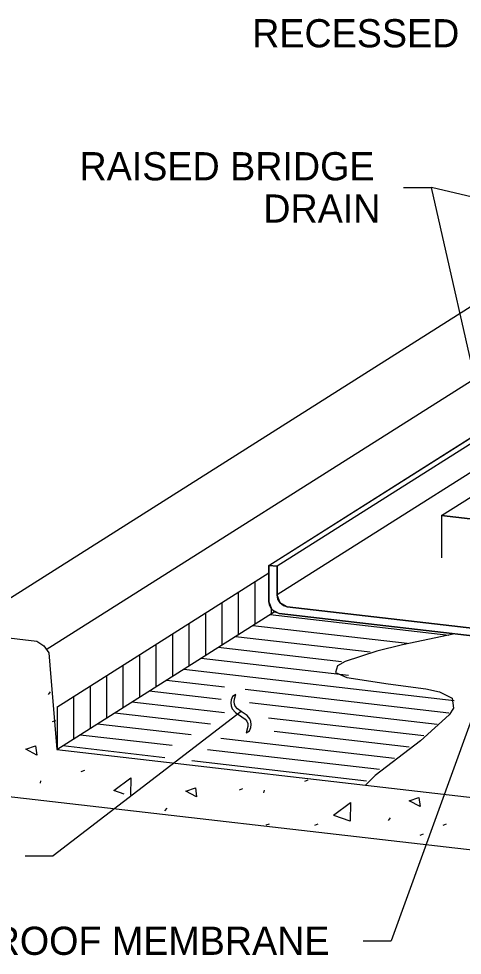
# Model space of a CAD drawing. Extents: x 99862 to 103151, y 100000 to 105076.
# Drawn here: x 102022 to 102274, y 103877 to 104409 of the extents above; entities that cross this region are included whole.
import ezdxf

# ---------------------------------------------------------------- set-up
doc = ezdxf.new("R2010")
doc.units = 0
for name, color, linetype in [('Level 1', 7, 'Continuous'), ('Level 15', 7, 'Continuous'), ('Level 20', 7, 'Continuous'), ('Level 3', 7, 'Continuous'), ('Level 4', 7, 'Continuous'), ('Level 7', 7, 'Continuous')]:
    doc.layers.add(name, color=color, linetype=linetype)

msp = doc.modelspace()

# ---------------------------------------------------------------- linework, layer by layer
at = {"layer": 'Level 1'}
for p, q in [((102262.02, 104126.8), (102262.02, 104102.75)), ((102163.91, 104098.53), (102168.59, 104097.99)), ((102163.91, 104080.79), (102163.91, 104098.53)), ((102163.91, 104077.87), (102163.91, 104080.79))]:
    msp.add_line(p, q, dxfattribs=at)
for points in [[(102481.21, 104118.78), (102369.43, 104048.12), (102169.65, 104071.2), (102167.45, 104071.91), (102165.59, 104073.42), (102164.35, 104075.52), (102163.91, 104077.87), (102163.91, 104098.53), (102350.74, 104216.63)], [(102163.91, 104077.87), (102163.91, 104080.79), (102163.91, 104098.53), (102350.24, 104216.31)], [(102350.24, 104212.81), (102168.59, 104097.99), (102168.59, 104081.69)], [(102350.24, 104196.51), (102168.59, 104081.69), (102169.03, 104079.34), (102170.27, 104077.24), (102172.13, 104075.73), (102174.33, 104075.02), (102369.43, 104052.48)], [(102262.02, 104126.8), (102303.73, 104153.17), (102352.43, 104147.54)], [(102262.02, 104126.8), (102310.72, 104121.17)], [(102310.72, 104097.12), (102310.72, 104121.17), (102262.02, 104126.8)], [(102163.91, 104098.53), (102163.91, 104077.87), (102163.91, 104077.87), (102165.59, 104073.42), (102169.65, 104071.2), (102169.65, 104071.2), (102369.43, 104048.12), (102369.43, 104048.12), (102369.43, 104052.48), (102369.43, 104052.48), (102174.33, 104075.02), (102174.33, 104075.02), (102170.27, 104077.24), (102168.59, 104081.69), (102168.59, 104081.69), (102168.59, 104097.99), (102168.59, 104097.99), (102163.91, 104098.53)], [(102174.33, 104075.02), (102172.13, 104075.73), (102170.27, 104077.24), (102169.03, 104079.34), (102168.59, 104081.69), (102168.59, 104097.99)]]:
    msp.add_lwpolyline(points, dxfattribs=at)
at = {"layer": 'Level 15'}
for p, q in [((102240.3, 104313.14), (102256.3, 104313.14)), ((102295.01, 104141.66), (102256.3, 104313.14)), ((102480.44, 104259.78), (102256.3, 104313.14)), ((102295.41, 104056.68), (102233.41, 103885.35)), ((102142.49, 104022.21), (102142.2, 104020.44)), ((102143.25, 104024.05), (102142.49, 104022.21)), ((102145.08, 104025.1), (102143.25, 104024.05)), ((102144.07, 104021.08), (102144.35, 104022.79)), ((102144.22, 104019.73), (102144.07, 104021.08)), ((102144.35, 104022.79), (102145.08, 104025.1)), ((102142.2, 104020.44), (102142.39, 104018.75)), ((102142.39, 104018.75), (102143.07, 104017.12)), ((102143.07, 104017.12), (102144.82, 104015.04)), ((102144.72, 104018.49), (102144.22, 104019.73)), ((102145.97, 104017.04), (102144.72, 104018.49)), ((102148.06, 104015.57), (102145.97, 104017.04)), ((102148.06, 104015.57), (102041.34, 103933.5)), ((102144.82, 104015.04), (102148.44, 104012.52)), ((102151.46, 104013.3), (102148.06, 104015.57)), ((102148.44, 104012.52), (102150.43, 104011.13)), ((102150.43, 104011.13), (102151.38, 104009.97)), ((102153.01, 104011.38), (102151.46, 104013.3)), ((102153.65, 104009.85), (102153.01, 104011.38)), ((102151.91, 104006.99), (102150.98, 104003.41)), ((102151.38, 104009.97), (102151.86, 104008.63)), ((102151.86, 104008.63), (102151.91, 104006.99)), ((102152.82, 104004.47), (102153.56, 104006.48)), ((102153.56, 104006.48), (102153.83, 104008.24)), ((102153.83, 104008.24), (102153.65, 104009.85)), ((102150.99, 104003.41), (102152.82, 104004.47)), ((102025.34, 103933.5), (102041.34, 103933.5)), ((102217.41, 103885.35), (102233.41, 103885.35))]:
    msp.add_line(p, q, dxfattribs=at)
at = {"layer": 'Level 3'}
for p, q in [((101986.04, 104060.75), (102533.58, 104406.86)), ((102037.31, 104050.75), (102586.57, 104397.94)), ((102043.41, 104018.07), (102163.91, 104094.24)), ((102043.41, 103994.04), (102167.41, 104072.42)), ((101986.04, 104060.75), (102031.94, 104055.45)), ((102031.94, 104055.45), (102035.9, 104052.73)), ((102035.9, 104052.73), (102038.72, 104048.76)), ((102038.72, 104048.76), (102039.45, 104041.94)), ((102039.45, 104041.94), (102043.41, 103994.04)), ((102039.6, 104026.75), (102038.42, 104025.28)), ((102040.96, 104009.79), (102042.87, 104010.52)), ((102043.41, 103994.04), (102387.68, 103954.27)), ((102057.27, 103981.43), (102059.18, 103982.16)), ((102034.11, 103976.25), (102033.82, 103974.78)), ((102184.27, 103976.06), (102186.18, 103976.79)), ((102387.68, 103924.23), (101985.53, 103970.69)), ((102081.53, 103968.51), (102075.74, 103970.64)), ((102147.1, 103971.09), (102149.01, 103971.82)), ((102161.11, 103970.88), (102160.82, 103969.41)), ((102105.78, 103960.56), (102104.61, 103959.09)), ((102162.24, 103951.1), (102164.15, 103951.83)), ((102232.78, 103955.19), (102231.6, 103953.72)), ((102189.9, 103950.98), (102191.81, 103951.72)), ((102262.84, 103950.98), (102264.75, 103951.72)), ((102249.81, 103945.33), (102251.73, 103946.06))]:
    msp.add_line(p, q, dxfattribs=at)
for points in [[(102025.82, 103994.07), (102031.26, 103995.97), (102032, 103990.83), (102025.82, 103994.07)], [(102075.79, 103970.63), (102085.36, 103977.86), (102085.2, 103968.02)], [(102116.63, 103970.26), (102122.07, 103972.17), (102122.8, 103967.03), (102116.63, 103970.26)], [(102200.62, 103956.66), (102210.18, 103963.89), (102210.01, 103953.2), (102200.81, 103956.57)], [(102243.63, 103964.89), (102249.06, 103966.8), (102249.8, 103961.66), (102243.63, 103964.89)]]:
    msp.add_lwpolyline(points, dxfattribs=at)
at = {"layer": 'Level 4'}
for p, q in [((102156.01, 104065.21), (102156.01, 104089.24)), ((102146.65, 104059.3), (102146.65, 104083.33)), ((102137.29, 104053.38), (102137.29, 104077.41)), ((102127.93, 104047.46), (102127.93, 104071.49)), ((102164.53, 104070.6), (102266.07, 104058.87)), ((102165.37, 104071.13), (102165.37, 104073.81)), ((102118.57, 104041.55), (102118.57, 104065.58)), ((102154.72, 104064.4), (102242.49, 104054.26)), ((102109.21, 104035.63), (102109.21, 104059.66)), ((102144.91, 104058.2), (102221.36, 104049.36)), ((102099.85, 104029.71), (102099.85, 104053.74)), ((102090.49, 104023.8), (102090.49, 104047.83)), ((102135.09, 104051.99), (102205.02, 104043.92)), ((102125.28, 104045.79), (102209.07, 104036.11)), ((102081.13, 104017.88), (102081.13, 104041.91)), ((102115.47, 104039.59), (102269.17, 104021.83)), ((102071.77, 104011.96), (102071.77, 104035.99)), ((102105.66, 104033.39), (102138.7, 104029.57)), ((102062.41, 104006.05), (102062.41, 104030.08)), ((102095.85, 104027.19), (102136.67, 104022.47)), ((102150.44, 104028.21), (102266.08, 104014.86)), ((102053.05, 104000.13), (102053.05, 104024.16)), ((102086.04, 104020.98), (102138.57, 104014.91)), ((102043.69, 103994.21), (102043.69, 104018.24)), ((102152.82, 104020.6), (102259.56, 104008.27)), ((102076.23, 104014.78), (102130.73, 104008.48)), ((102163.65, 104012.02), (102251.88, 104001.83)), ((102066.41, 104008.58), (102119.77, 104002.42)), ((102056.6, 104002.38), (102108.86, 103996.34)), ((102136.58, 104000.47), (102235.17, 103989.08)), ((102166.81, 104004.32), (102243.64, 103995.44)), ((102046.79, 103996.18), (102104.7, 103989.49)), ((102128.98, 103994.02), (102226.76, 103982.72)), ((102120.12, 103987.7), (102219.33, 103976.24))]:
    msp.add_line(p, q, dxfattribs=at)
msp.add_lwpolyline([(102269.54, 104059.66), (102239.81, 104053.35), (102225.26, 104049.75), (102207.12, 104043.85), (102202.77, 104041.46), (102201.64, 104037.66), (102208.09, 104034.89), (102231.67, 104031.31), (102253.05, 104028.49), (102260.8, 104026.76), (102267.91, 104023.1), (102268.67, 104017.49), (102266.36, 104013.71), (102249.97, 103998.82), (102224.2, 103979.19), (102218.74, 103973.79)], dxfattribs=at)
at = {"layer": 'Level 7'}
msp.add_lwpolyline([(102169.65, 104071.2), (102167.45, 104071.91), (102165.59, 104073.42), (102164.35, 104075.52), (102164.23, 104076.18)], dxfattribs=at)

# ---------------------------------------------------------------- texts
at = {"layer": 'Level 20'}
for s, p in [('RECESSED DRAIN', (102154.36, 104392.66)), ('RAISED BRIDGE ', (102056.24, 104317.14)), ('DRAIN', (102160.68, 104293.14)), ('WATERPROOF MEMBRANE', (101915.37, 103877.35))]:
    msp.add_text(s, height=16, dxfattribs=at).set_placement(p)

doc.saveas('drawing.dxf')
